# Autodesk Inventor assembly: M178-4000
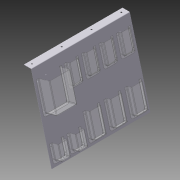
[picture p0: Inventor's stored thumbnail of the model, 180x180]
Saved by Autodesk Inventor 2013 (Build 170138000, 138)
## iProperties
Created: 2004-11
Part Number: M178-4000
Document SubType Name: Assembly
Designer: Autodesk, Inc.
Manufacturer: Standard
Standards Organization: Custom
Description: TOOL CADDY
Mass: 1512.37 g
Surface Area: 9103.48 cm^2
Volume: 746.122 cm^3
Density: 2.02698 g/cm^3
CAGE: 1LJX3
Dept. ID: Product Design
Description #2: ---
Finish #1: ---
Finish #2: ---
Material ID: ---
Project Number: ---
Author: Autodesk, Inc.
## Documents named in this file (13)
- Z:\_DATEN\Test Station\Components\M178-4000.iam
- Z:\_DATEN\Test Station\Components\Tool Cady Ref Mount Bar.ipt
- Z:\_DATEN\Test Station\Components\M178-4002.ipt
- Z:\_DATEN\Test Station\Components\MS20470 A 4-5.ipt
- Z:\_DATEN\Test Station\Components\M178-4001-11.ipt
- Z:\_DATEN\Test Station\Components\M178-4001-09.ipt
- Z:\_DATEN\Test Station\Components\M178-4003.ipt
- Z:\_DATEN\Test Station\Components\M178-4001-01.ipt
- Z:\_DATEN\Test Station\Components\M178-4001-07.ipt
- Z:\_DATEN\Test Station\Components\M178-4001-03.ipt
- C:\Users\kelleyb.ADS\Desktop\Samples MIGRATED 2009 224 RTM_1\Standard Parts\Test Station Content\Extrusions\40 Series Profiles.ipt
- C:\Users\kelleyb.ADS\Desktop\Samples MIGRATED 2009 224 RTM_1\Models\Assemblies\Test Station\Components\Parts\M178-4001-XX.ipt
- C:\Users\kelleyb.ADS\Desktop\Samples MIGRATED 2009 224 RTM_1\Standard Parts\Test Station Content\Rivets\MS204xx Rivets.ipt
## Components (24 placed, 9 different names)
1. Tool Cady Ref Mount Bar:1 — Flush:1, Flush:2
2. M178-4002:1 — Flush:1, Flush:2, Flush:3, Insert:1, Insert:2, Insert:8, Insert:9, Insert:12, Insert:13, Insert:14, Insert:15, Insert:16, Insert:17, Insert:24, Insert:25
3. M178-4001-07:1 — Insert:8, Insert:9
4. M178-4001-11:6 — Insert:1, Insert:2, Insert:18, Insert:19, Insert:20, Insert:21, Insert:22, Insert:23
5. MS20470 A 4-5:1 — Insert:18
6. MS20470 A 4-5:2 — Insert:19
7. MS20470 A 4-5:3 — Insert:23
8. MS20470 A 4-5:4 — Insert:22
9. MS20470 A 4-5:5 — Insert:20
10. MS20470 A 4-5:6 — Insert:21
11. M178-4003:1 — Insert:26, Insert:27
12. MS20470 A 4-5:8 — Insert:24, Insert:26
13. MS20470 A 4-5:7 — Insert:25, Insert:27
14. M178-4003:3
15. MS20470 A 4-5:9
16. MS20470 A 4-5:10
17. M178-4001-03:7 — Insert:16, Insert:17
18. M178-4001-03:2
19. M178-4001-03:3
20. M178-4001-01:8 — Insert:12, Insert:13
21. M178-4001-01:9
22. M178-4001-09:10 — Insert:14, Insert:15
23. M178-4001-09:4
24. M178-4001-09:5
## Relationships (23: Insert 20, Flush 3)
- Flush:1: Tool Cady Ref Mount Bar:1 ↔ M178-4002:1
- Flush:2: Tool Cady Ref Mount Bar:1 ↔ M178-4002:1
- Flush:3: M178-4002:1
- Insert:1: M178-4002:1 ↔ M178-4001-11:6
- Insert:2: M178-4002:1 ↔ M178-4001-11:6
- Insert:8: M178-4002:1 ↔ M178-4001-07:1
- Insert:9: M178-4002:1 ↔ M178-4001-07:1
- Insert:12: M178-4002:1 ↔ M178-4001-01:8
- Insert:13: M178-4002:1 ↔ M178-4001-01:8
- Insert:14: M178-4002:1 ↔ M178-4001-09:10
- Insert:15: M178-4002:1 ↔ M178-4001-09:10
- Insert:16: M178-4002:1 ↔ M178-4001-03:7
- Insert:17: M178-4002:1 ↔ M178-4001-03:7
- Insert:18: M178-4001-11:6 ↔ MS20470 A 4-5:1
- Insert:19: M178-4001-11:6 ↔ MS20470 A 4-5:2
- Insert:20: M178-4001-11:6 ↔ MS20470 A 4-5:5
- Insert:21: M178-4001-11:6 ↔ MS20470 A 4-5:6
- Insert:22: M178-4001-11:6 ↔ MS20470 A 4-5:4
- Insert:23: M178-4001-11:6 ↔ MS20470 A 4-5:3
- Insert:24: M178-4002:1 ↔ MS20470 A 4-5:8
- Insert:25: M178-4002:1 ↔ MS20470 A 4-5:7
- Insert:26: M178-4003:1 ↔ MS20470 A 4-5:8
- Insert:27: M178-4003:1 ↔ MS20470 A 4-5:7
